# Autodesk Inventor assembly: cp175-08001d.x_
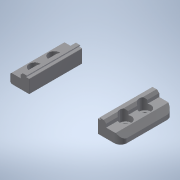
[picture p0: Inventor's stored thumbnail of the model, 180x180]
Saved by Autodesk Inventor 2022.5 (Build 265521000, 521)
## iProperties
Part Number: cp175-08001d.x_
Material: 一般
Document SubType Name: Assembly
Designer: ImaoCorp
Sending System: SOLIDWORKS 2017-2017317
MC: AMD64
MC_MODEL: Intel64 Family 6 Model 60 Stepping 3, GenuineIntel
OS: Windows_NT
FRU: Parasolid Version 29.0, build 201,  4-17-2017
FORMAT: text
GUISE: transmit
KEY: cp175-08001d
FILE: cp175-08001d.x_t
DATE: Thu Jul 18 11:19:13 2019
Author: ImaoCorp
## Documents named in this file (3)
- X:\14_SW2022-Inv2022\00_全2023-1023新製品(TCC)まで\c\cp175-08001d\CP175-08001D.iam
- X:\14_SW2022-Inv2022\00_全2023-1023新製品(TCC)まで\c\cp175-08001d\cp175-08001d_01.ipt
- X:\14_SW2022-Inv2022\00_全2023-1023新製品(TCC)まで\c\cp175-08001d\cp175-08001d_02.ipt
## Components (2 placed, 2 different names)
1. cp175-08001d_01
2. cp175-08001d_02
